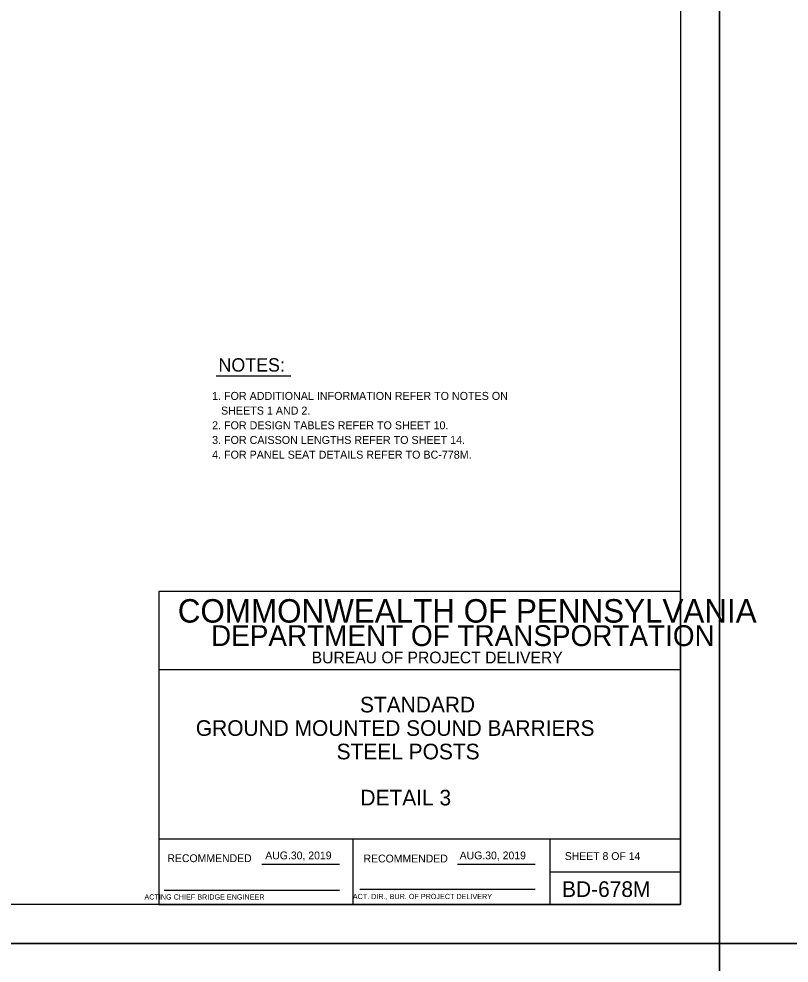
# Model space of a CAD drawing. Extents: x 3475 to 6558, y -3780 to 1166.
# Drawn here: x 4333.6 to 4629, y -1811.8 to -1449.6 of the extents above; entities that cross this region are included whole.
import ezdxf

# ---------------------------------------------------------------- set-up
doc = ezdxf.new("R2010")
doc.units = 0
for name, color, linetype in [('1', 7, 'Continuous'), ('2', 7, 'Continuous'), ('PLT-BNDY', 7, 'Continuous')]:
    doc.layers.add(name, color=color, linetype=linetype)

msp = doc.modelspace()

# ---------------------------------------------------------------- linework, layer by layer
at = {"layer": '1'}
msp.add_line((4409.36, -1586.5), (4437.93, -1586.5), dxfattribs=at)
at = {"layer": '2'}
for p, q in [((4587.34, -1225.31), (4587.34, -1789.31)), ((4587.34, -1669.31), (4387.34, -1669.31)), ((4387.34, -1669.31), (4387.34, -1789.31)), ((4587.34, -1789.31), (4587.34, -1669.31)), ((4587.34, -1699.31), (4387.34, -1699.31)), ((4587.34, -1764.31), (4387.34, -1764.31)), ((4461.84, -1789.31), (4461.84, -1764.31)), ((4537.34, -1764.31), (4537.34, -1789.31)), ((4426.81, -1773.81), (4456.57, -1773.81)), ((4501.81, -1773.81), (4531.71, -1773.81)), ((4537.34, -1776.81), (4587.34, -1776.81)), ((4389.34, -1783.81), (4456.57, -1783.81)), ((4464.47, -1783.43), (4531.71, -1783.43)), ((4587.34, -1789.31), (3801.34, -1789.31)), ((4387.34, -1789.31), (4587.34, -1789.31))]:
    msp.add_line(p, q, dxfattribs=at)
at = {"layer": 'PLT-BNDY'}
for points in [[(3761.34, -1210.31), (4602.34, -1210.31), (4602.34, -1804.31), (3761.34, -1804.31)], [(4602.34, -1210.31), (5443.34, -1210.31), (5443.34, -1804.31), (4602.34, -1804.31)], [(3761.34, -1804.31), (4602.34, -1804.31), (4602.34, -2398.31), (3761.34, -2398.31)], [(4602.34, -1804.31), (5443.34, -1804.31), (5443.34, -2398.31), (4602.34, -2398.31)]]:
    msp.add_lwpolyline(points, close=True, dxfattribs=at)

# ---------------------------------------------------------------- texts
at = {"layer": '1'}
for s, height, p in [('NOTES:', 5.117, (4410.2, -1584.88)), ('1. FOR ADDITIONAL INFORMATION REFER TO NOTES ON', 3.072, (4407.76, -1595.76)), ('   SHEETS 1 AND 2.', 3.072, (4407.76, -1601.39)), ('2. FOR DESIGN TABLES REFER TO SHEET 10.', 3.072, (4407.76, -1607.02)), ('3. FOR CAISSON LENGTHS REFER TO SHEET 14.', 3.072, (4407.76, -1612.65)), ('4. FOR PANEL SEAT DETAILS REFER TO BC-778M.', 3.072, (4407.76, -1618.29)), ('STANDARD', 6, (4464.48, -1715.64)), ('GROUND MOUNTED SOUND BARRIERS', 6.0001, (4401.5, -1724.64)), ('STEEL POSTS', 6.0001, (4455.5, -1733.64)), ('DETAIL 3', 6, (4464.64, -1751.31)), ('SHEET 8 OF 14', 3, (4543.01, -1772.25)), ('BD-678M', 6, (4541.97, -1786.43))]:
    msp.add_text(s, height=height, dxfattribs=at).set_placement(p)
at = {"layer": '2'}
for s, height, p in [('COMMONWEALTH OF PENNSYLVANIA', 9, (4394.59, -1681.18)), ('DEPARTMENT OF TRANSPORTATION', 8.0002, (4407.34, -1690.18)), ('BUREAU OF PROJECT DELIVERY', 4.5, (4445.93, -1696.81)), ('AUG.30, 2019', 3, (4428.14, -1772)), ('AUG.30, 2019', 3, (4502.69, -1772)), ('       ACTING CHIEF BRIDGE ENGINEER', 2.0002, (4376.43, -1787.43)), ('   ACT. DIR., BUR. OF PROJECT DELIVERY', 2.0002, (4459.41, -1787.25))]:
    msp.add_text(s, height=height, dxfattribs=at).set_placement(p)
for p in [(4390.61, -1773.06), (4465.83, -1773.18)]:
    msp.add_text('RECOMMENDED', height=3, rotation=360, dxfattribs=at).set_placement(p)

doc.saveas('drawing.dxf')
